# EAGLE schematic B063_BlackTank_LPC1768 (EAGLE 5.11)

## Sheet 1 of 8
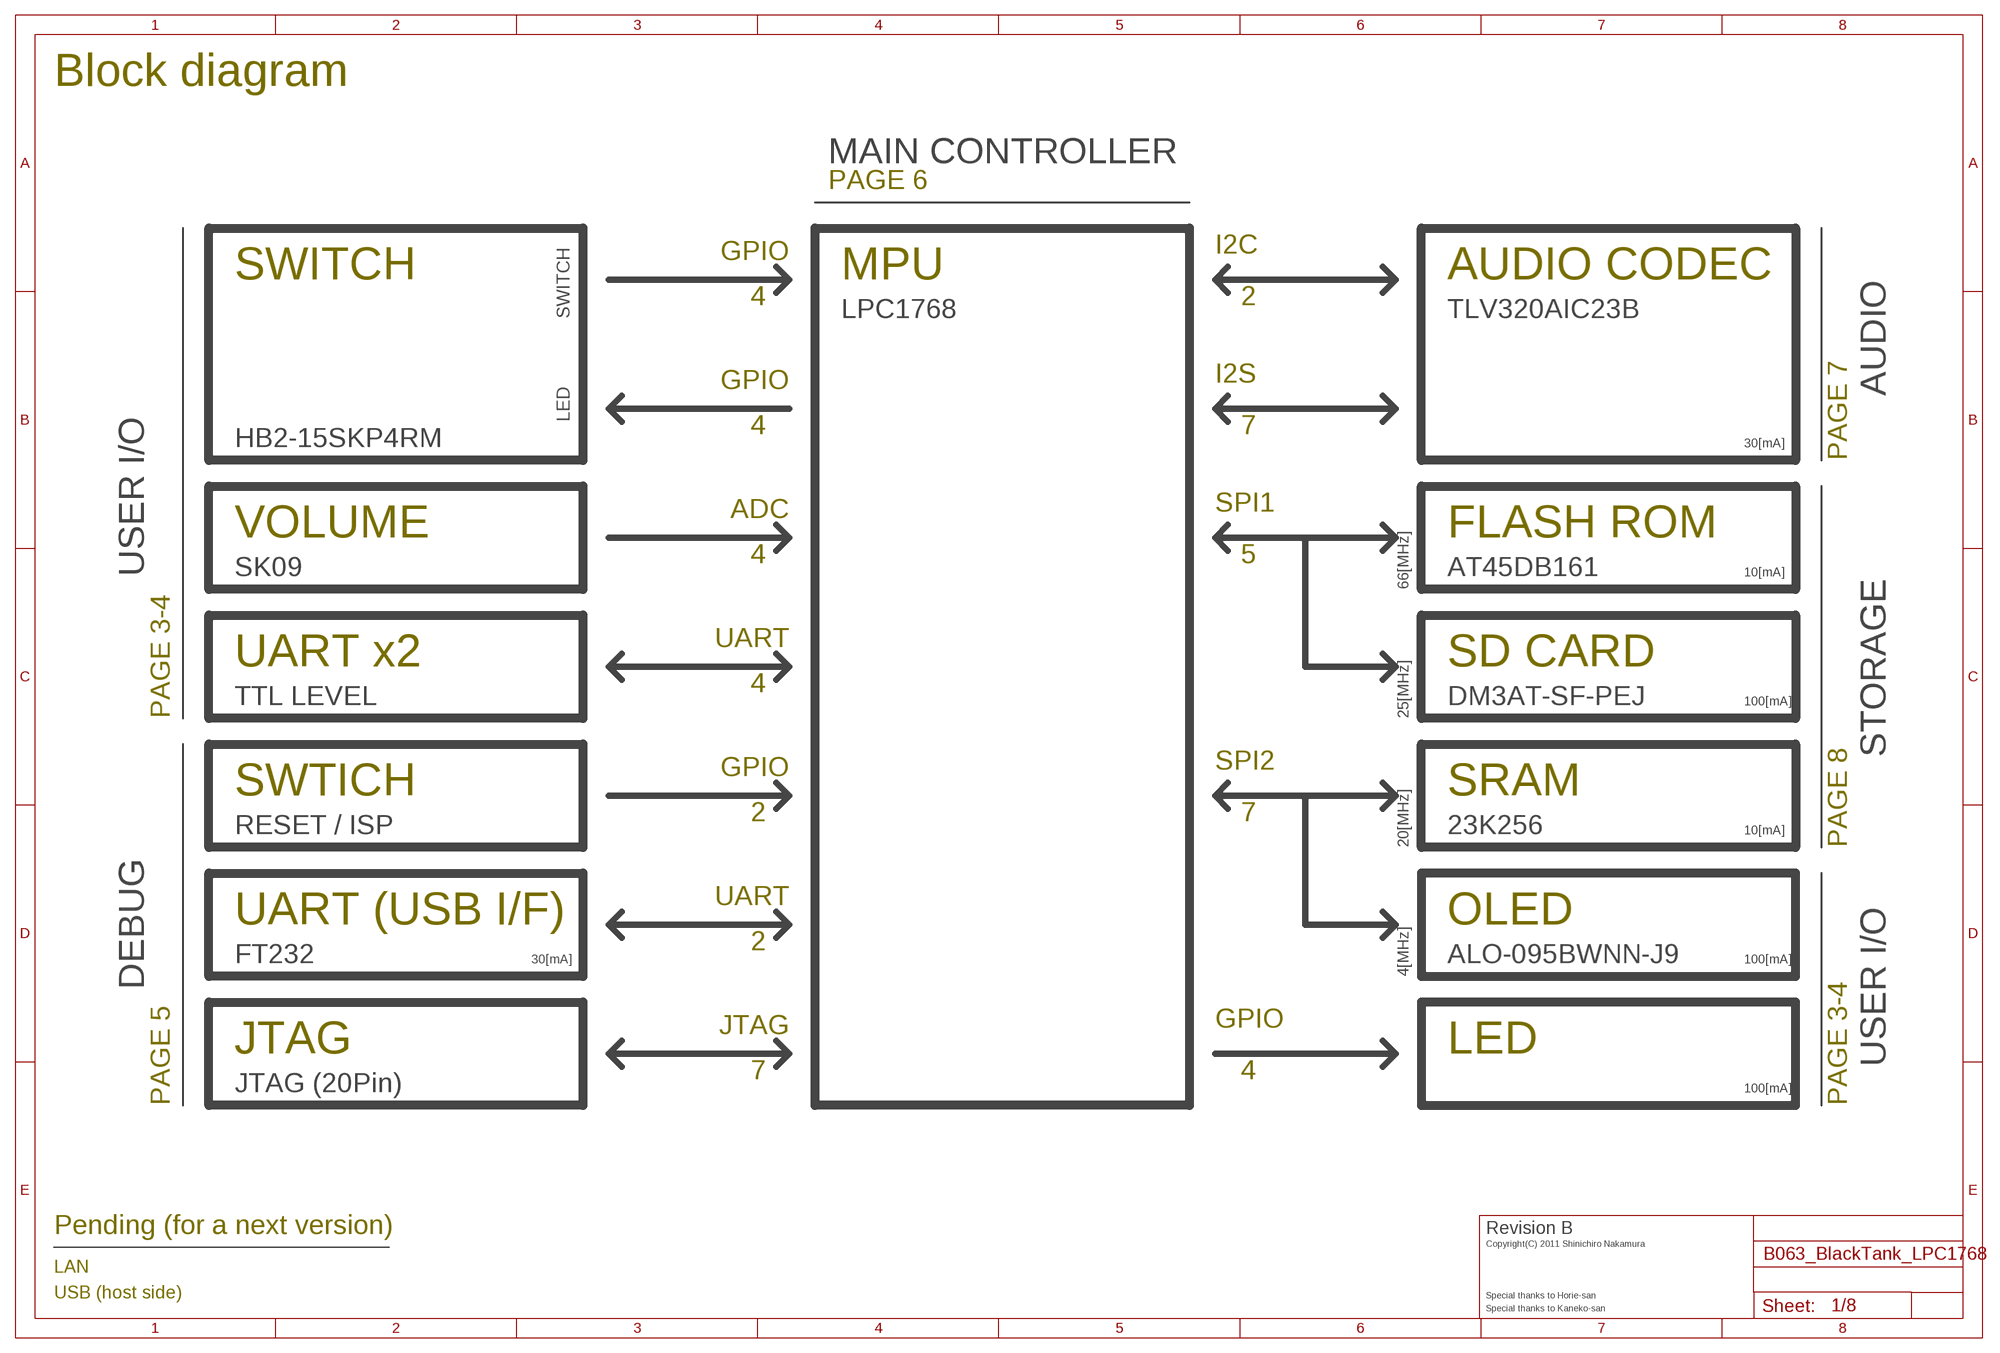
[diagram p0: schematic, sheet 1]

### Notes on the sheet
- Block diagram
- MAIN CONTROLLER
- PAGE 6
- GPIO
- I2C
- SWITCH | MPU | AUDIO CODEC
- 4 | 2
- SWITCH | LPC1768 | TLV320AIC23B
- GPIO
- I2S
- AUDIO
- LED
- 4 | 7
- HB2-15SKP4RM | 30[mA]
- PAGE 7
- ADC
- SPI1
- VOLUME | FLASH ROM
- 4 | 5
- USER I/O | SK09 | AT45DB161 | 10[mA]
- 66[MHz]
- UART
- UART x2 | SD CARD
- 4
- TTL LEVEL | DM3AT-SF-PEJ | 100[mA]
- PAGE 3-4 | 25[MHz]
- GPIO | STORAGE
- SPI2
- SWTICH | SRAM
- 2 | 7
- RESET / ISP | 23K256 | 10[mA]
- 20[MHz] | PAGE 8
- UART
- UART (USB I/F) | OLED
- 2
- FT232 | 30[mA] | ALO-095BWNN-J9 | 100[mA]
- 4[MHz]
- DEBUG
- JTAG
- GPIO
- JTAG | LED
- USER I/O
- 7 | 4
- JTAG (20Pin) | 100[mA]
- PAGE 5 | PAGE 3-4
- Pending (for a next version) | Revision B
- Copyright(C) 2011 Shinichiro Nakamura
- LAN
- USB (host side) | Special thanks to Horie-san
- Special thanks to Kaneko-san

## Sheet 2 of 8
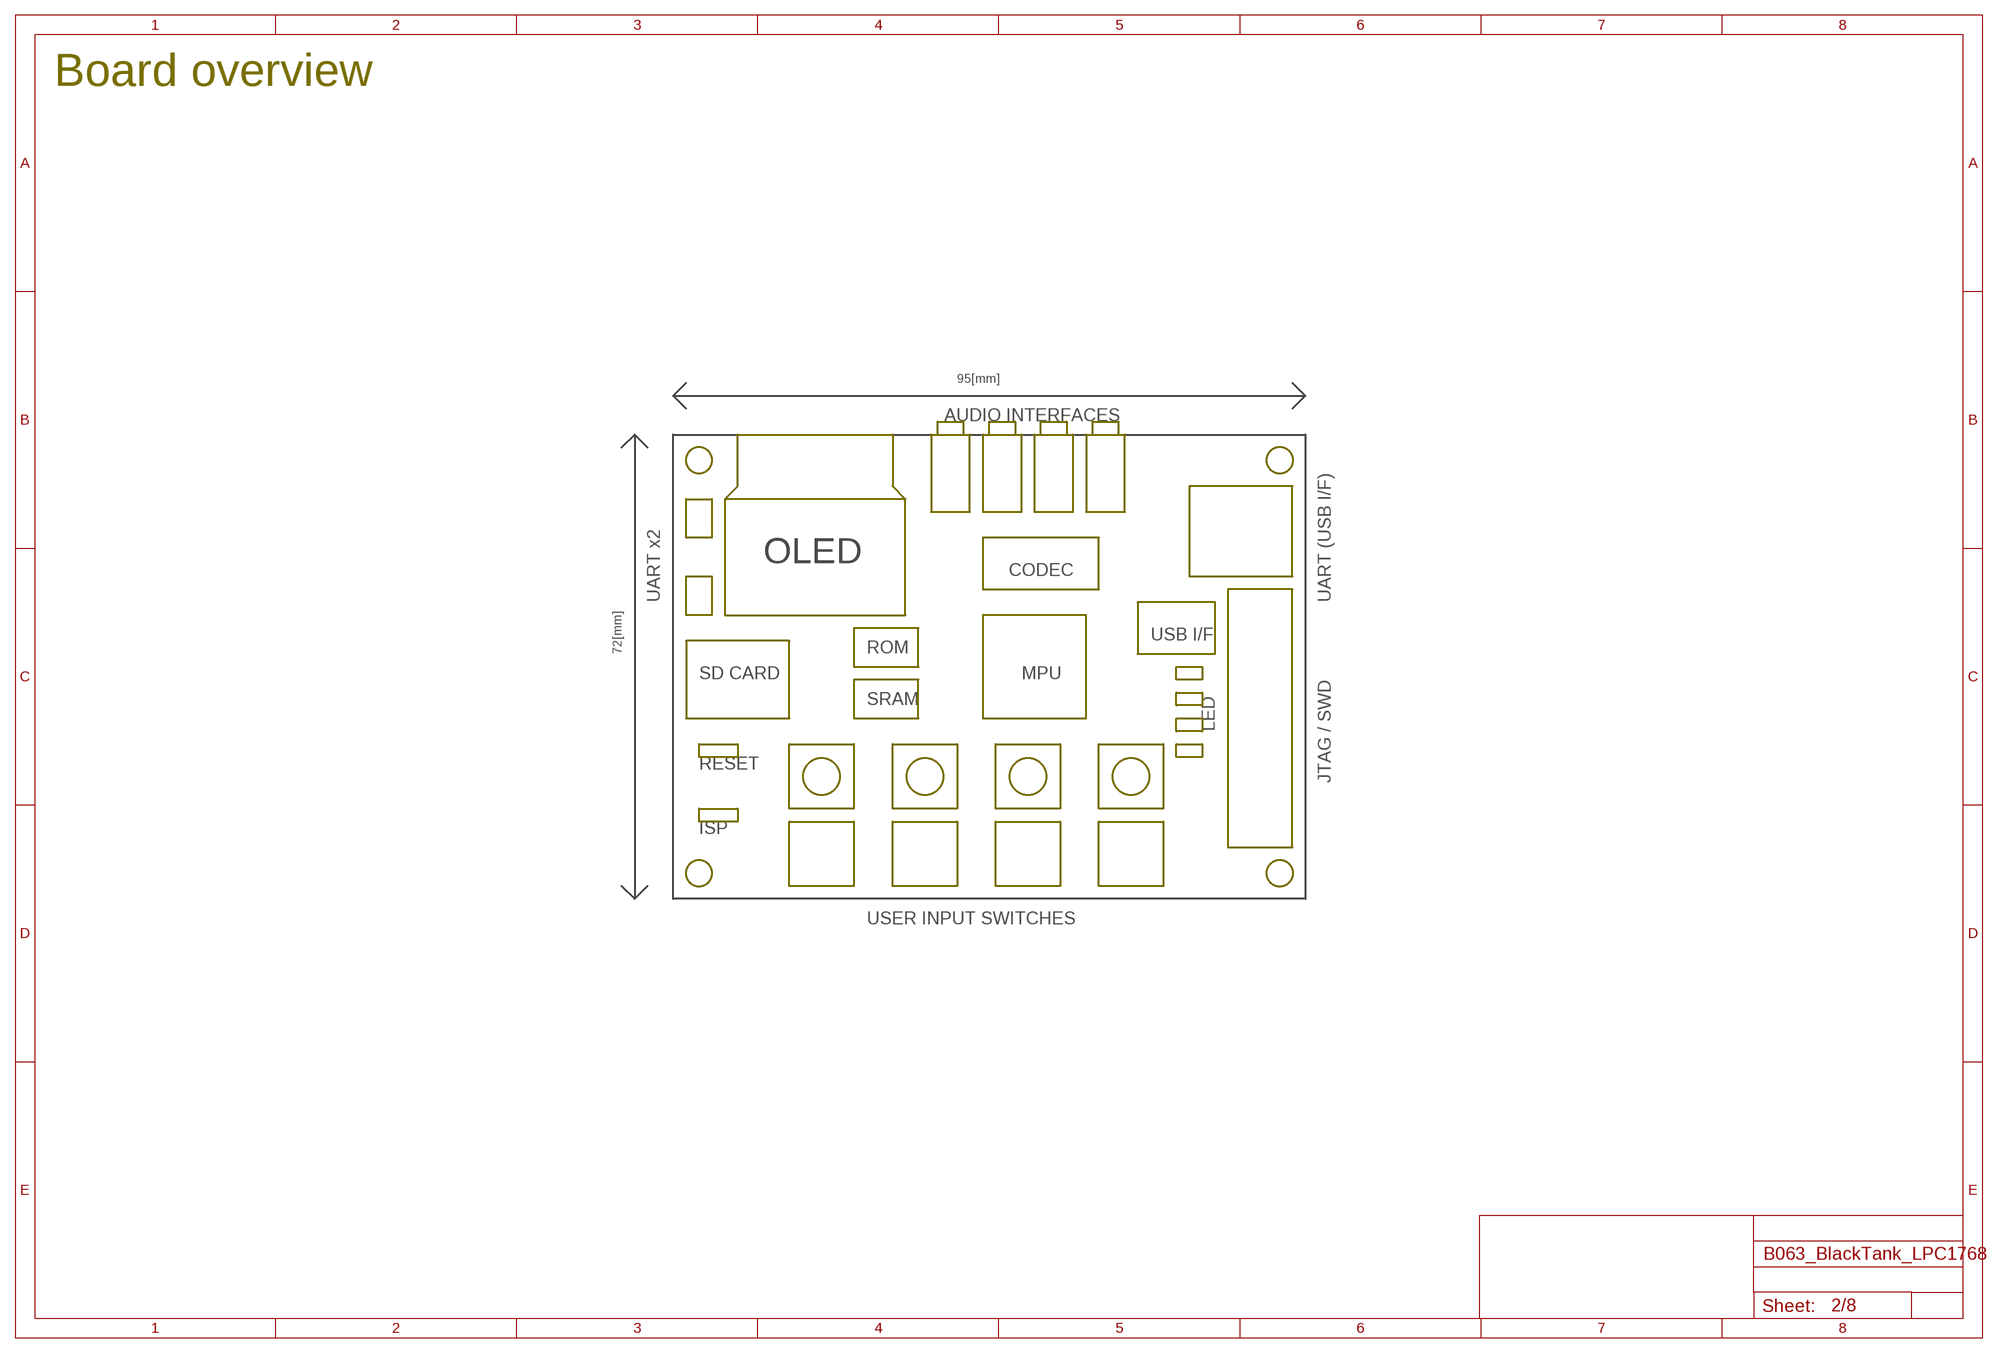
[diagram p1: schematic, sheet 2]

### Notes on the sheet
- Board overview
- 95[mm]
- AUDIO INTERFACES
- OLED
- CODEC
- UART x2 | UART (USB I/F)
- USB I/F
- 72[mm] | ROM
- SD CARD | MPU
- SRAM
- LED
- RESET
- JTAG / SWD
- ISP
- USER INPUT SWITCHES

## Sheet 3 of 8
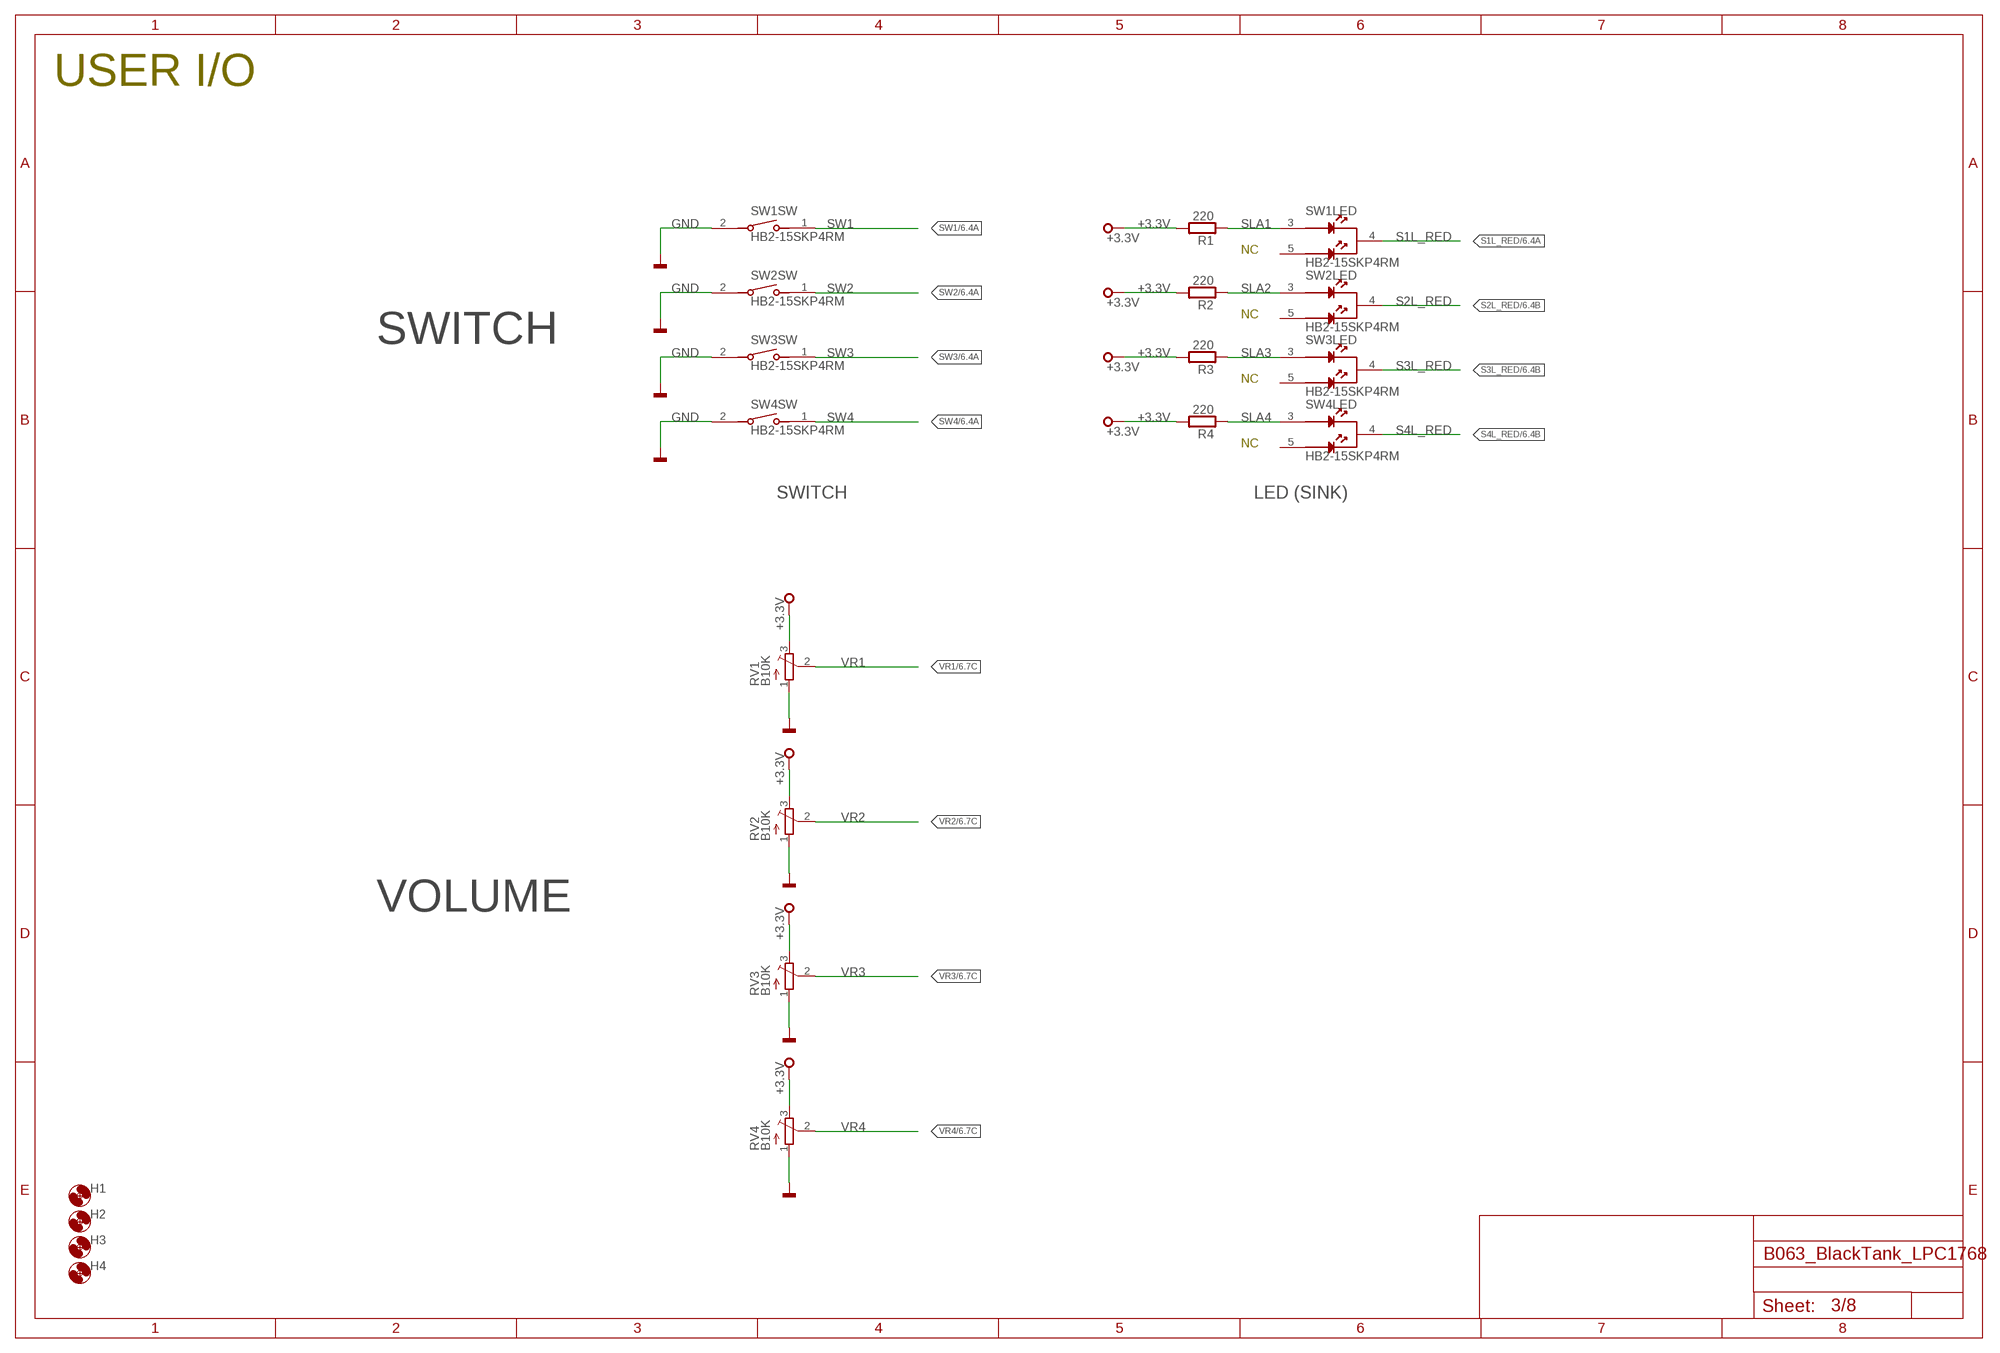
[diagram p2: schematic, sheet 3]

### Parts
H1  MOUNT-HOLE3.2  [3,2]
H2  MOUNT-HOLE3.2  [3,2]
H3  MOUNT-HOLE3.2  [3,2]
H4  MOUNT-HOLE3.2  [3,2]
R1  220  R0603  [0603]
R2  220  R0603  [0603]
R3  220  R0603  [0603]
R4  220  R0603  [0603]
RV1  B10K  RK09  [SK09]
RV2  B10K  RK09  [SK09]
RV3  B10K  RK09  [SK09]
RV4  B10K  RK09  [SK09]
SW1  HB2-15SKP4RM  [HB2]
SW2  HB2-15SKP4RM  [HB2]
SW3  HB2-15SKP4RM  [HB2]
SW4  HB2-15SKP4RM  [HB2]

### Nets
+3.3V [PWR]: R1.2 R2.2 R3.2 R4.2 RV1.3(R1) RV2.3(R1) RV3.3(R1) RV4.3(R1) ; also sheet 4,5,6,7,8
GND [GND]: RV1.1(R2) RV2.1(R2) RV3.1(R2) RV4.1(R2) SW1.2 SW2.2 SW3.2 SW4.2 ; also sheet 4,5,6,7,8
S1L_RED: SW1.4(LED:C) ; also sheet 6
S2L_RED: SW2.4(LED:C) ; also sheet 6
S3L_RED: SW3.4(LED:C) ; also sheet 6
S4L_RED: SW4.4(LED:C) ; also sheet 6
SLA1: R1.1 SW1.3(LED:A1)
SLA2: R2.1 SW2.3(LED:A1)
SLA3: R3.1 SW3.3(LED:A1)
SLA4: R4.1 SW4.3(LED:A1)
SW1: SW1.1 ; also sheet 6
SW2: SW2.1 ; also sheet 6
SW3: SW3.1 ; also sheet 6
SW4: SW4.1 ; also sheet 6
VR1: RV1.2(P) ; also sheet 6
VR2: RV2.2(P) ; also sheet 6
VR3: RV3.2(P) ; also sheet 6
VR4: RV4.2(P) ; also sheet 6
Unconnected: SW1.5(LED:A2) SW2.5(LED:A2) SW3.5(LED:A2) SW4.5(LED:A2)

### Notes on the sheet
- USER I/O
- NC
- NC
- SWITCH
- NC
- NC
- SWITCH | LED (SINK)
- VOLUME

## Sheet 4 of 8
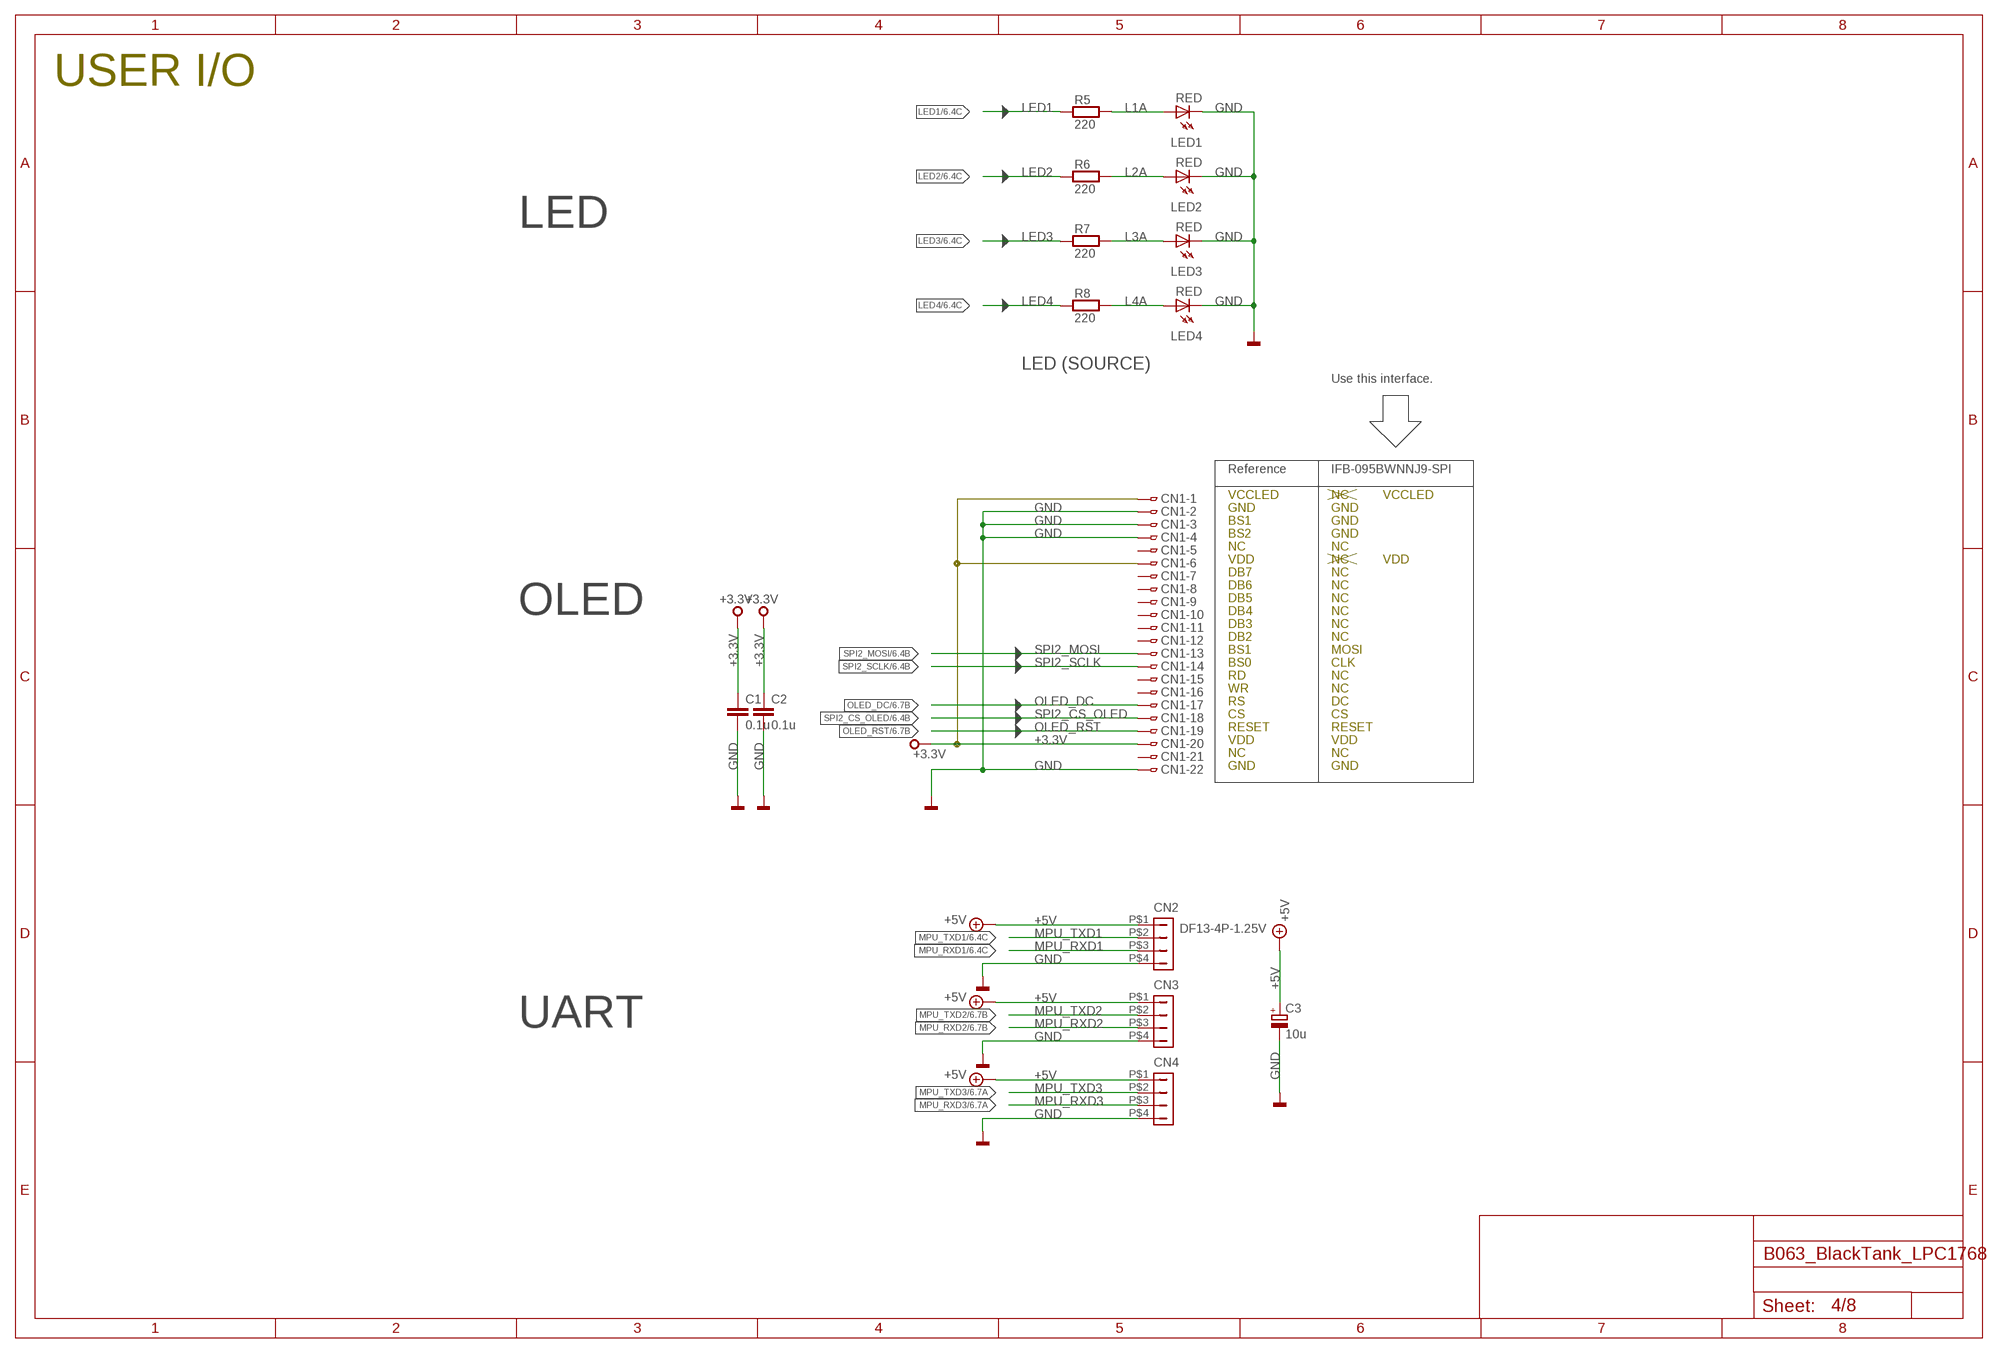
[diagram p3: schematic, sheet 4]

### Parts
C1  0.1u  C-EUC0603  [C0603]
C2  0.1u  C-EUC0603  [C0603]
C3  10u  CPOL-EU153CLV-0505  [153CLV-0505]
CN1  FH12-22S-0.5SH  [FH12-22S-0.5SH]
CN2  DF13-4P-1.25V  [DF13C-4P-1.25V]
CN3  DF13-4P-1.25V  [DF13C-4P-1.25V]
CN4  DF13-4P-1.25V  [DF13C-4P-1.25V]
LED1  RED  LED_0805  [LED_0805]
LED2  RED  LED_0805  [LED_0805]
LED3  RED  LED_0805  [LED_0805]
LED4  RED  LED_0805  [LED_0805]
R5  220  R0603  [0603]
R6  220  R0603  [0603]
R7  220  R0603  [0603]
R8  220  R0603  [0603]

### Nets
+3.3V [PWR]: C1.1 C2.1 CN1.20 ; also sheet 3,5,6,7,8
+5V [PWR]: C3.+ CN2.P$1 CN3.P$1 CN4.P$1 ; also sheet 5
GND [GND]: C1.2 C2.2 C3.- CN1.2 CN1.3 CN1.4 CN1.22 CN2.P$4 CN3.P$4 CN4.P$4 LED1.K LED2.K LED3.K LED4.K ; also sheet 3,5,6,7,8
L1A: LED1.A R5.2
L2A: LED2.A R6.2
L3A: LED3.A R7.2
L4A: LED4.A R8.2
LED1: R5.1 ; also sheet 6
LED2: R6.1 ; also sheet 6
LED3: R7.1 ; also sheet 6
LED4: R8.1 ; also sheet 6
MPU_RXD1: CN2.P$3 ; also sheet 6
MPU_RXD2: CN3.P$3 ; also sheet 6
MPU_RXD3: CN4.P$3 ; also sheet 6
MPU_TXD1: CN2.P$2 ; also sheet 6
MPU_TXD2: CN3.P$2 ; also sheet 6
MPU_TXD3: CN4.P$2 ; also sheet 6
OLED_DC: CN1.17 ; also sheet 6
OLED_RST: CN1.19 ; also sheet 6
SPI2_CS_OLED: CN1.18 ; also sheet 6
SPI2_MOSI: CN1.13 ; also sheet 6,8
SPI2_SCLK: CN1.14 ; also sheet 6,8
Unconnected: CN1.1 CN1.5 CN1.6 CN1.7 CN1.8 CN1.9 CN1.10 CN1.11 CN1.12 CN1.15 CN1.16 CN1.21

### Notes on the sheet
- USER I/O
- LED
- LED (SOURCE)
- Use this interface.
- Reference | IFB-095BWNNJ9-SPI
- VCCLED | NC | VCCLED
- GND | GND
- BS1 | GND
- BS2 | GND
- NC | NC
- VDD | NC | VDD
- DB7 | NC
- DB6 | NC
- DB5 | NC
- OLED | DB4 | NC
- DB3 | NC
- DB2 | NC
- BS1 | MOSI
- BS0 | CLK
- RD | NC
- WR | NC
- RS | DC
- CS | CS
- RESET | RESET
- VDD | VDD
- NC | NC
- GND | GND
- UART

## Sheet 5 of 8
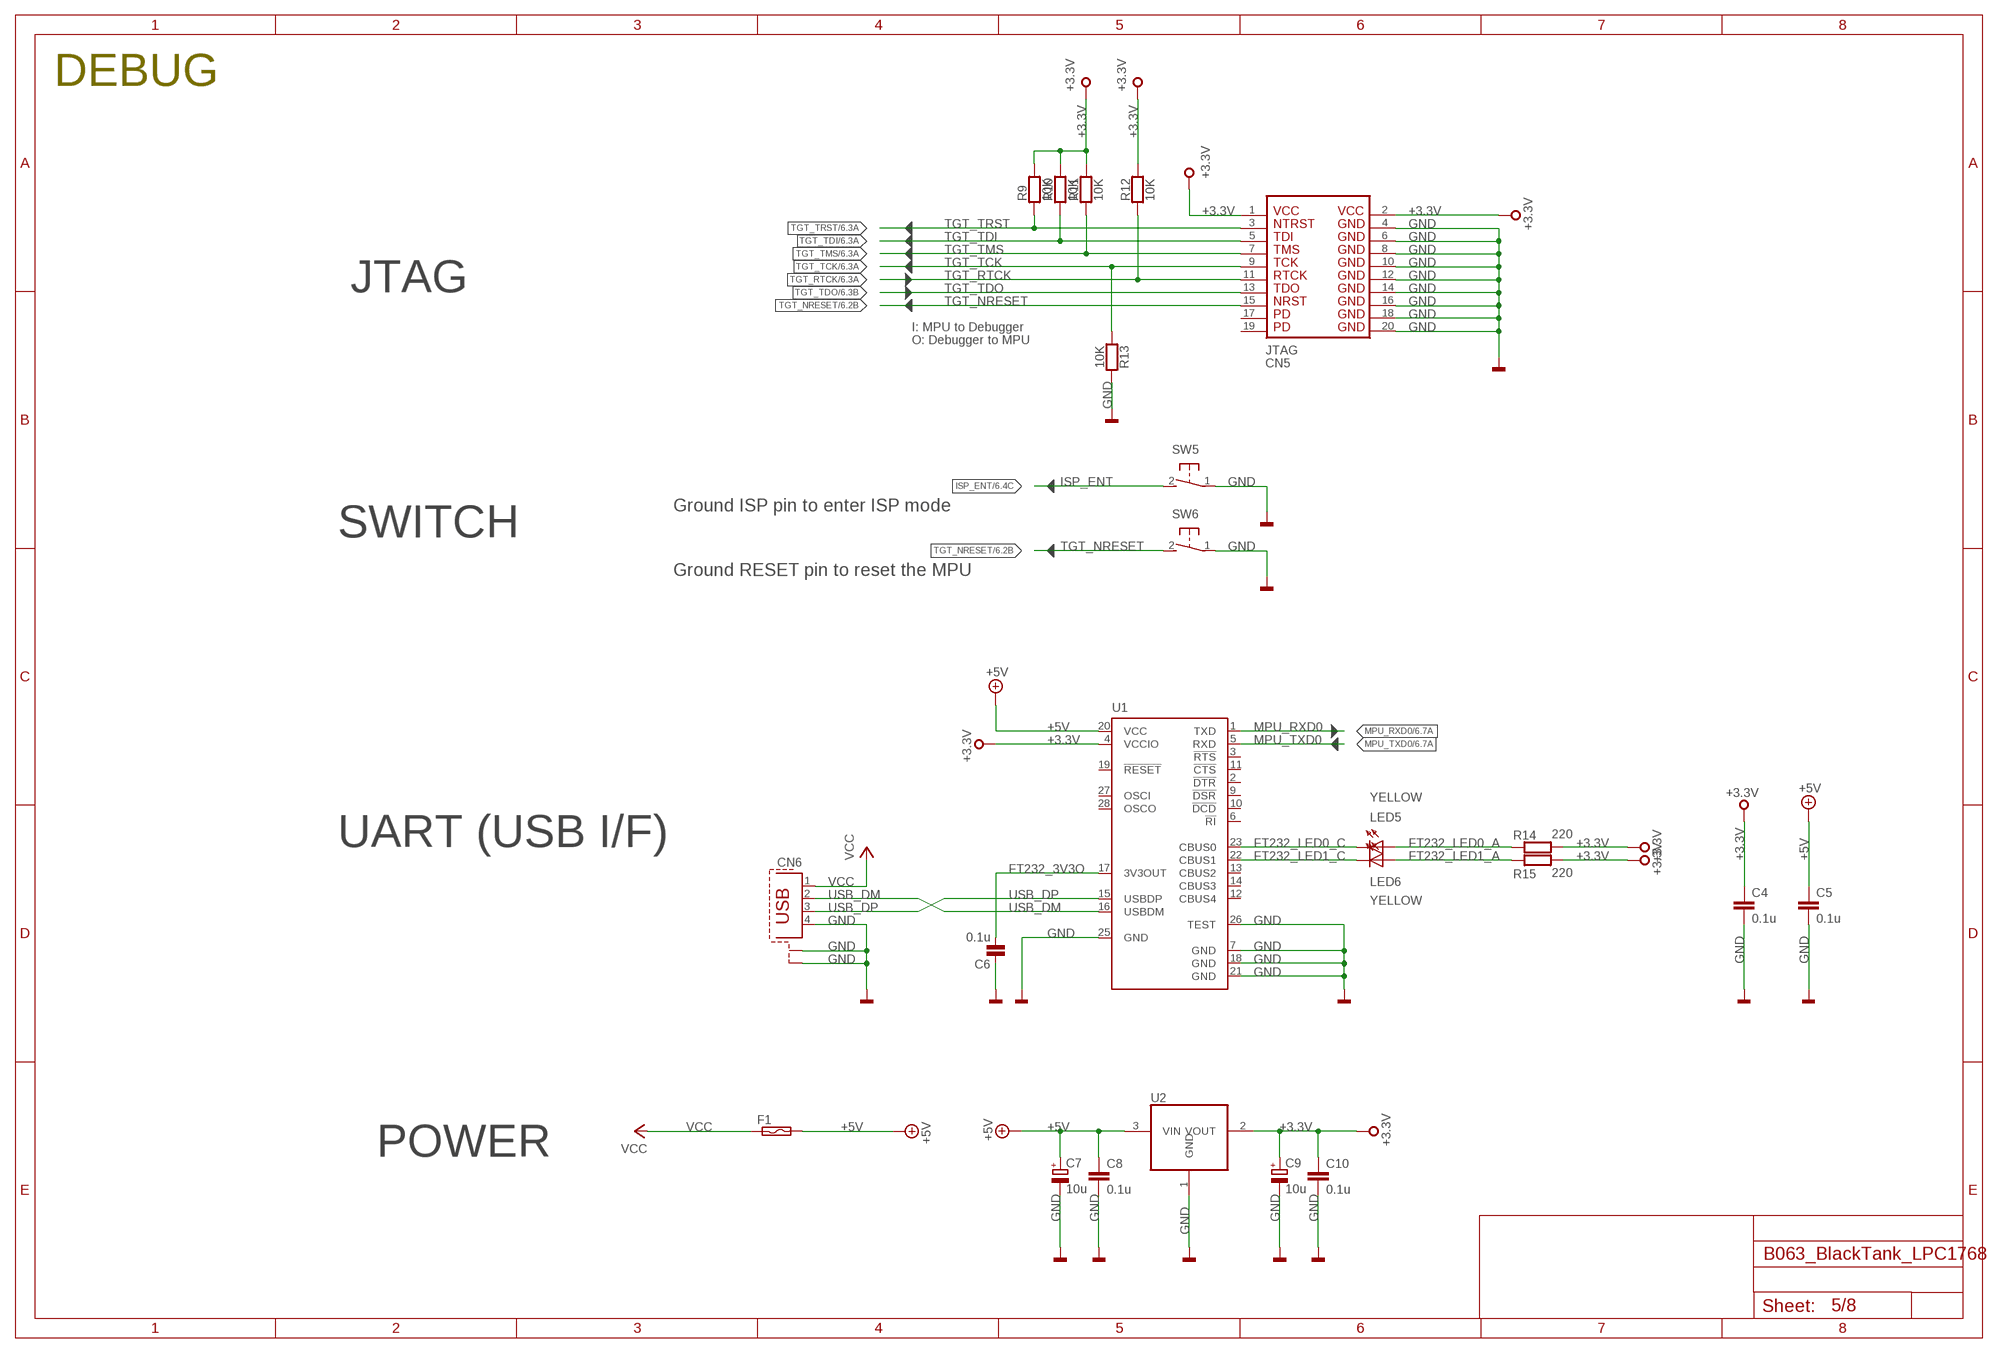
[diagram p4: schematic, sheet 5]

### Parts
C4  0.1u  C-EUC0603  [C0603]
C5  0.1u  C-EUC0603  [C0603]
C6  0.1u  C0603  [0603]
C7  10u  CPOL-EU153CLV-0505  [153CLV-0505]
C8  0.1u  C-EUC0603  [C0603]
C9  10u  CPOL-EU153CLV-0505  [153CLV-0505]
C10  0.1u  C-EUC0603  [C0603]
CN5  JTAG-20  [JTAG-20]
CN6  PN61729-S  [PN61729-S]
F1  SMD075F  [SMD050F]
LED5  YELLOW  LED_0805  [LED_0805]
LED6  YELLOW  LED_0805  [LED_0805]
R9  10K  R0603  [0603]
R10  10K  R0603  [0603]
R11  10K  R0603  [0603]
R12  10K  R0603  [0603]
R13  10K  R0603  [0603]
R14  220  R0603  [0603]
R15  220  R0603  [0603]
SW5  DTSM-3  [DTSM-3]
SW6  DTSM-3  [DTSM-3]
U1  FT232RL  [SSOP28]
U2  REG1117  [SOT223]

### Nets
+3.3V [PWR]: C4.1 C9.+ C10.1 CN5.1 CN5.2 R9.2 R10.2 R11.2 R12.2 R14.1 R15.1 U1.4(VCCIO) U2.2(VOUT) ; also sheet 3,4,6,7,8
+5V [PWR]: C5.1 C7.+ C8.1 F1.2 U1.20(VCC) U2.3(VIN) ; also sheet 4
FT232_3V3O: C6.2 U1.17(3V3OUT)
FT232_LED0_A: LED5.A R14.2
FT232_LED0_C: LED5.K U1.23(CBUS0)
FT232_LED1_A: LED6.A R15.2
FT232_LED1_C: LED6.K U1.22(CBUS1)
GND [GND]: C4.2 C5.2 C6.1 C7.- C8.2 C9.- C10.2 CN5.4 CN5.6 CN5.8 CN5.10 CN5.12 CN5.14 CN5.16 CN5.18 CN5.20 CN6.4 CN6.S1 CN6.S2 R13.2 SW5.1 SW6.1 U1.7(GND) U1.18(GND) U1.21(GND) U1.25(GND) U1.26(TEST) U2.1(GND) ; also sheet 3,4,6,7,8
ISP_ENT: SW5.2 ; also sheet 6
MPU_RXD0: U1.1(TXD) ; also sheet 6
MPU_TXD0: U1.5(RXD) ; also sheet 6
TGT_NRESET: CN5.15 SW6.2 ; also sheet 6
TGT_RTCK: CN5.11 R12.1 ; also sheet 6
TGT_TCK: CN5.9 R13.1 ; also sheet 6
TGT_TDI: CN5.5 R10.1 ; also sheet 6
TGT_TDO: CN5.13 ; also sheet 6
TGT_TMS: CN5.7 R11.1 ; also sheet 6
TGT_TRST: CN5.3 R9.1 ; also sheet 6
USB_DM: CN6.2 U1.16(USBDM)
USB_DP: CN6.3 U1.15(USBDP)
VCC [PWR]: CN6.1 F1.1
Unconnected: CN5.17 CN5.19 U1.2(!DTR) U1.3(!RTS) U1.6(!RI) U1.9(!DSR) U1.10(!DCD) U1.11(!CTS) U1.12(CBUS4) U1.13(CBUS2) U1.14(CBUS3) U1.19(!RESET) U1.27(OSCI) U1.28(OSCO)

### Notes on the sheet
- DEBUG
- JTAG
- I: MPU to Debugger
- O: Debugger to MPU
- Ground ISP pin to enter ISP mode
- SWITCH
- Ground RESET pin to reset the MPU
- UART (USB I/F)
- POWER

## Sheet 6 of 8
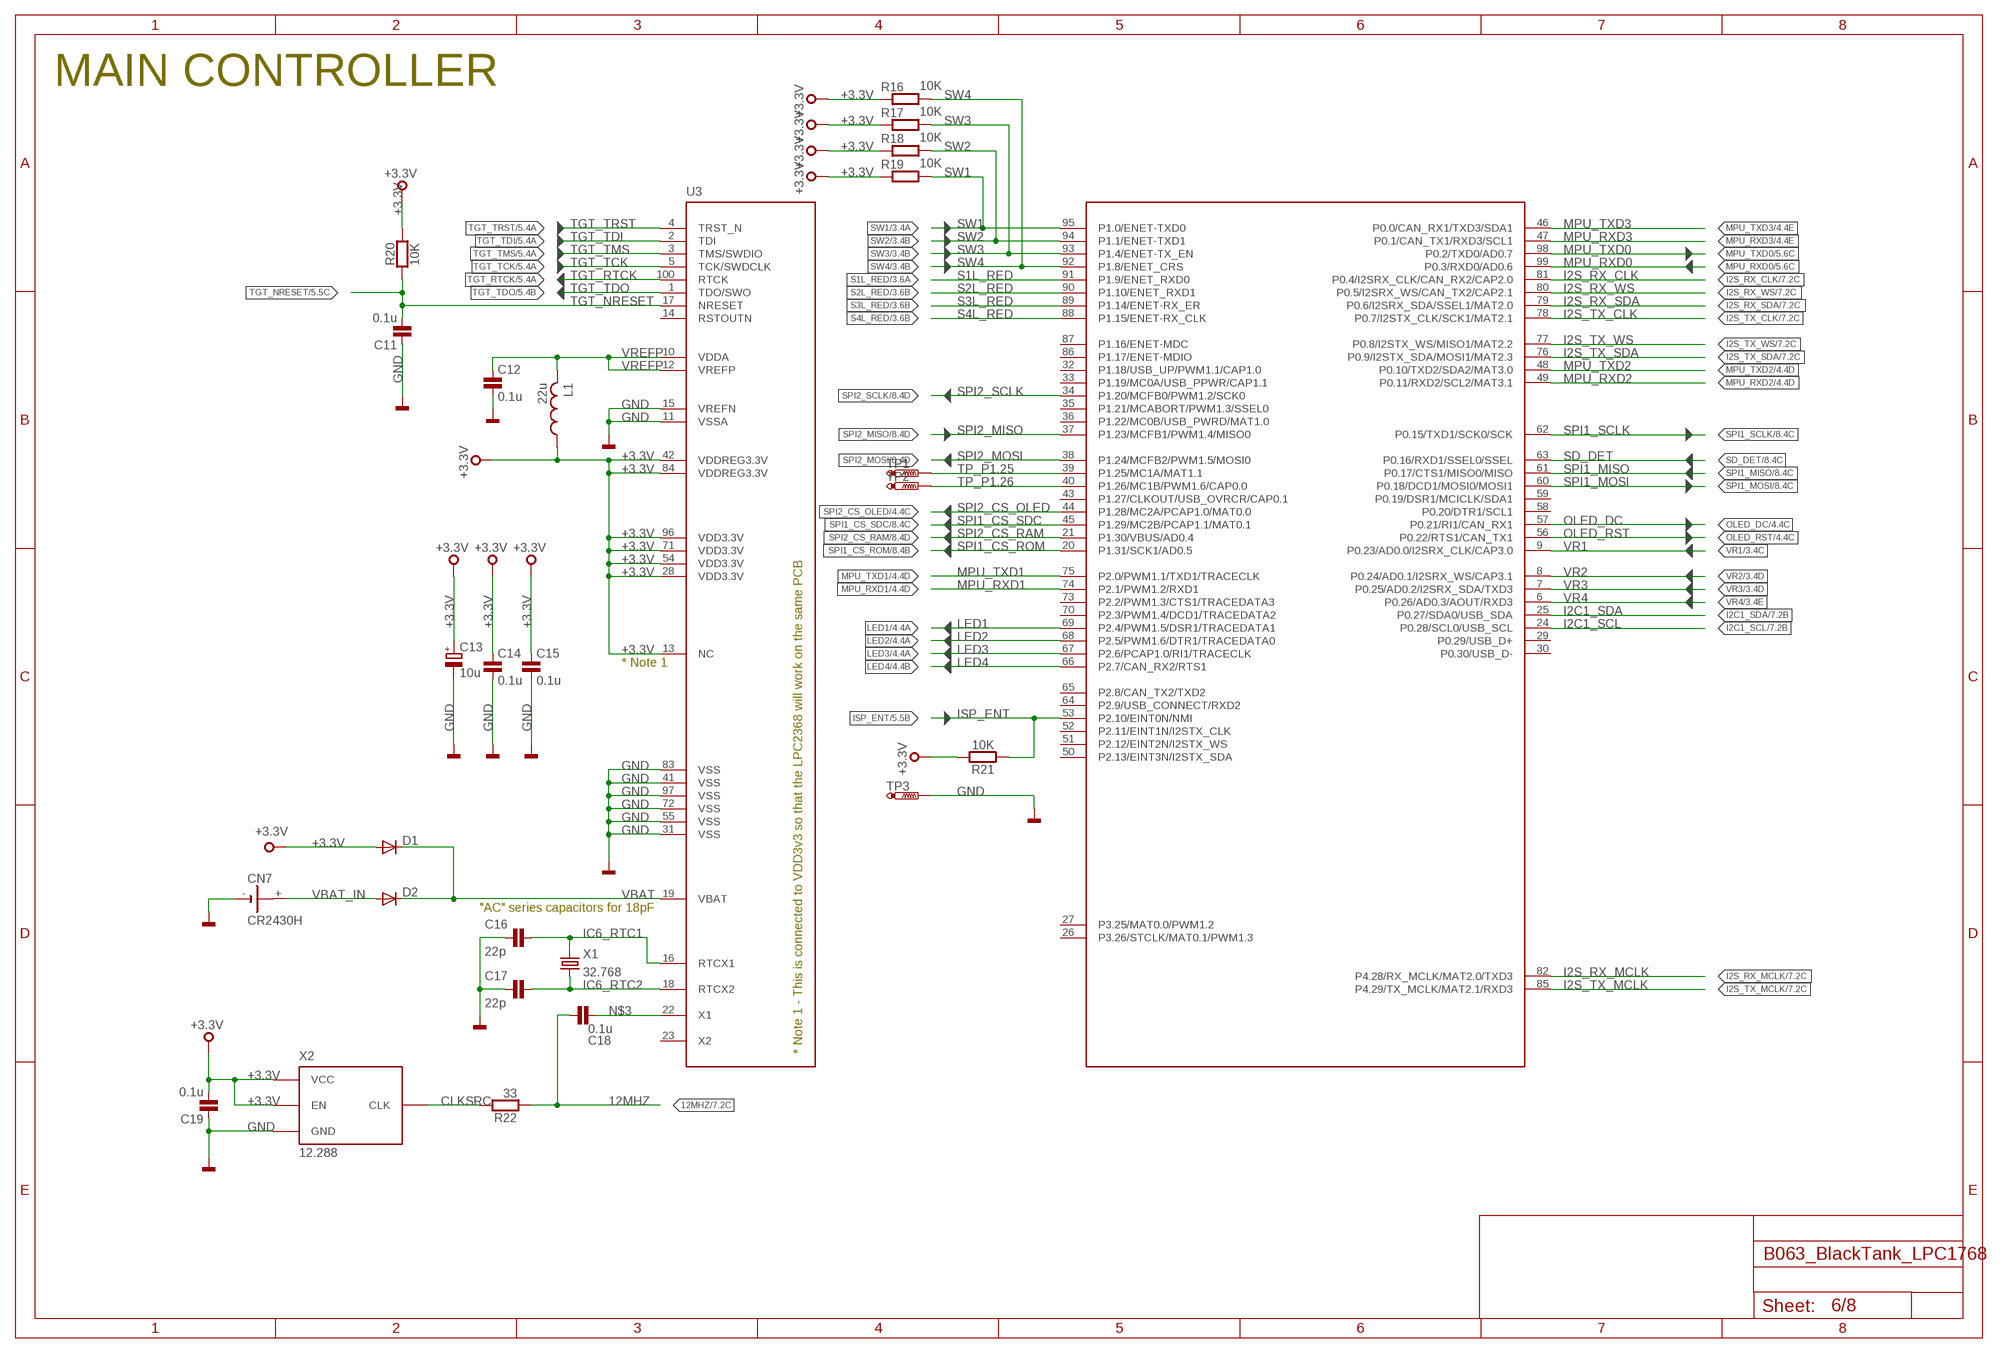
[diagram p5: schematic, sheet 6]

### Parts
C11  0.1u  C0603  [0603]
C12  0.1u  C0603  [0603]
C13  10u  CPOL-EU153CLV-0505  [153CLV-0505]
C14  0.1u  C0603  [0603]
C15  0.1u  C0603  [0603]
C16  22p  C0603  [0603]
C17  22p  C0603  [0603]
C18  0.1u  C0603  [0603]
C19  0.1u  C0603  [0603]
CN7  CR2430H  [CR2430H]
D1  MBR0520LT  [SOD123]
D2  MBR0520LT  [SOD123]
L1  22u  L-USL3230M  [L3230M]
R16  10K  R0603  [0603]
R17  10K  R0603  [0603]
R18  10K  R0603  [0603]
R19  10K  R0603  [0603]
R20  10K  R0603  [0603]
R21  10K  R0603  [0603]
R22  33  R0603  [0603]
TP1  PTR1PAD1-13  [P1-13]
TP2  PTR1PAD1-13  [P1-13]
TP3  PTR1PAD1-13  [P1-13]
U3  LPC1768  [LQFP100]
X1  32.768  CRYSTALFC135  [FC135]
X2  12.288  OSCILLATOR_2.5X3.2  [OSC3.2X.2.5]

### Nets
12MHZ: C18.1 R22.1 ; also sheet 7
+3.3V [PWR]: C13.+ C14.1 C15.1 C19.2 D1.A L1.1 R16.2 R17.2 R18.2 R19.2 R20.2 R21.2 U3.13(NC) U3.28(VDD3.3V) U3.42(VDDREG3.3V) U3.54(VDD3.3V) U3.71(VDD3.3V) U3.84(VDDREG3.3V) U3.96(VDD3.3V) X2.P$1(EN) X2.P$4(VCC) ; also sheet 3,4,5,7,8
CLKSRC: R22.2 X2.P$3(CLK)
GND [GND]: C11.1 C12.2 C13.- C14.2 C15.2 C16.1 C17.1 C19.1 CN7.- TP3.TP U3.11(VSSA) U3.15(VREFN) U3.31(VSS) U3.41(VSS) U3.55(VSS) U3.72(VSS) U3.83(VSS) U3.97(VSS) X2.P$2(GND) ; also sheet 3,4,5,7,8
I2C1_SCL: U3.24(P0.28/SCL0/USB_SCL) ; also sheet 7
I2C1_SDA: U3.25(P0.27/SDA0/USB_SDA) ; also sheet 7
I2S_RX_CLK: U3.81(P0.4/I2SRX_CLK/CAN_RX2/CAP2.0) ; also sheet 7
I2S_RX_MCLK: U3.82(P4.28/RX_MCLK/MAT2.0/TXD3) ; also sheet 7
I2S_RX_SDA: U3.79(P0.6/I2SRX_SDA/SSEL1/MAT2.0) ; also sheet 7
I2S_RX_WS: U3.80(P0.5/I2SRX_WS/CAN_TX2/CAP2.1) ; also sheet 7
I2S_TX_CLK: U3.78(P0.7/I2STX_CLK/SCK1/MAT2.1) ; also sheet 7
I2S_TX_MCLK: U3.85(P4.29/TX_MCLK/MAT2.1/RXD3) ; also sheet 7
I2S_TX_SDA: U3.76(P0.9/I2STX_SDA/MOSI1/MAT2.3) ; also sheet 7
I2S_TX_WS: U3.77(P0.8/I2STX_WS/MISO1/MAT2.2) ; also sheet 7
IC6_RTC1: C16.2 U3.16(RTCX1) X1.X2
IC6_RTC2: C17.2 U3.18(RTCX2) X1.X1
ISP_ENT: R21.1 U3.53(P2.10/EINT0N/NMI) ; also sheet 5
LED1: U3.69(P2.4/PWM1.5/DSR1/TRACEDATA1) ; also sheet 4
LED2: U3.68(P2.5/PWM1.6/DTR1/TRACEDATA0) ; also sheet 4
LED3: U3.67(P2.6/PCAP1.0/RI1/TRACECLK) ; also sheet 4
LED4: U3.66(P2.7/CAN_RX2/RTS1) ; also sheet 4
MPU_RXD0: U3.99(P0.3/RXD0/AD0.6) ; also sheet 5
MPU_RXD1: U3.74(P2.1/PWM1.2/RXD1) ; also sheet 4
MPU_RXD2: U3.49(P0.11/RXD2/SCL2/MAT3.1) ; also sheet 4
MPU_RXD3: U3.47(P0.1/CAN_TX1/RXD3/SCL1) ; also sheet 4
MPU_TXD0: U3.98(P0.2/TXD0/AD0.7) ; also sheet 5
MPU_TXD1: U3.75(P2.0/PWM1.1/TXD1/TRACECLK) ; also sheet 4
MPU_TXD2: U3.48(P0.10/TXD2/SDA2/MAT3.0) ; also sheet 4
MPU_TXD3: U3.46(P0.0/CAN_RX1/TXD3/SDA1) ; also sheet 4
N$3: C18.2 U3.22(X1)
OLED_DC: U3.57(P0.21/RI1/CAN_RX1) ; also sheet 4
OLED_RST: U3.56(P0.22/RTS1/CAN_TX1) ; also sheet 4
S1L_RED: U3.91(P1.9/ENET_RXD0) ; also sheet 3
S2L_RED: U3.90(P1.10/ENET_RXD1) ; also sheet 3
S3L_RED: U3.89(P1.14/ENET-RX_ER) ; also sheet 3
S4L_RED: U3.88(P1.15/ENET-RX_CLK) ; also sheet 3
SD_DET: U3.63(P0.16/RXD1/SSEL0/SSEL) ; also sheet 8
SPI1_CS_ROM: U3.20(P1.31/SCK1/AD0.5) ; also sheet 8
SPI1_CS_SDC: U3.45(P1.29/MC2B/PCAP1.1/MAT0.1) ; also sheet 8
SPI1_MISO: U3.61(P0.17/CTS1/MISO0/MISO) ; also sheet 8
SPI1_MOSI: U3.60(P0.18/DCD1/MOSI0/MOSI1) ; also sheet 8
SPI1_SCLK: U3.62(P0.15/TXD1/SCK0/SCK) ; also sheet 8
SPI2_CS_OLED: U3.44(P1.28/MC2A/PCAP1.0/MAT0.0) ; also sheet 4
SPI2_CS_RAM: U3.21(P1.30/VBUS/AD0.4) ; also sheet 8
SPI2_MISO: U3.37(P1.23/MCFB1/PWM1.4/MISO0) ; also sheet 8
SPI2_MOSI: U3.38(P1.24/MCFB2/PWM1.5/MOSI0) ; also sheet 4,8
SPI2_SCLK: U3.34(P1.20/MCFB0/PWM1.2/SCK0) ; also sheet 4,8
SW1: R19.1 U3.95(P1.0/ENET-TXD0) ; also sheet 3
SW2: R18.1 U3.94(P1.1/ENET-TXD1) ; also sheet 3
SW3: R17.1 U3.93(P1.4/ENET-TX_EN) ; also sheet 3
SW4: R16.1 U3.92(P1.8/ENET_CRS) ; also sheet 3
TGT_NRESET: C11.2 R20.1 U3.17(NRESET) ; also sheet 5
TGT_RTCK: U3.100(RTCK) ; also sheet 5
TGT_TCK: U3.5(TCK/SWDCLK) ; also sheet 5
TGT_TDI: U3.2(TDI) ; also sheet 5
TGT_TDO: U3.1(TDO/SWO) ; also sheet 5
TGT_TMS: U3.3(TMS/SWDIO) ; also sheet 5
TGT_TRST: U3.4(TRST_N) ; also sheet 5
TP_P1.25: TP1.TP U3.39(P1.25/MC1A/MAT1.1)
TP_P1.26: TP2.TP U3.40(P1.26/MC1B/PWM1.6/CAP0.0)
VBAT [PWR]: D1.C D2.C U3.19(VBAT)
VBAT_IN [PWR]: CN7.+ D2.A
VR1: U3.9(P0.23/AD0.0/I2SRX_CLK/CAP3.0) ; also sheet 3
VR2: U3.8(P0.24/AD0.1/I2SRX_WS/CAP3.1) ; also sheet 3
VR3: U3.7(P0.25/AD0.2/I2SRX_SDA/TXD3) ; also sheet 3
VR4: U3.6(P0.26/AD0.3/AOUT/RXD3) ; also sheet 3
VREFP: C12.1 L1.2 U3.10(VDDA) U3.12(VREFP)
Unconnected: CN7.+@1(+) U3.14(RSTOUTN) U3.23(X2) U3.26(P3.26/STCLK/MAT0.1/PWM1.3) U3.27(P3.25/MAT0.0/PWM1.2) U3.29(P0.29/USB_D+) U3.30(P0.30/USB_D-) U3.32(P1.18/USB_UP/PWM1.1/CAP1.0) U3.33(P1.19/MC0A/USB_PPWR/CAP1.1) U3.35(P1.21/MCABORT/PWM1.3/SSEL0) U3.36(P1.22/MC0B/USB_PWRD/MAT1.0) U3.43(P1.27/CLKOUT/USB_OVRCR/CAP0.1) U3.50(P2.13/EINT3N/I2STX_SDA) U3.51(P2.12/EINT2N/I2STX_WS) U3.52(P2.11/EINT1N/I2STX_CLK) U3.58(P0.20/DTR1/SCL1) U3.59(P0.19/DSR1/MCICLK/SDA1) U3.64(P2.9/USB_CONNECT/RXD2) U3.65(P2.8/CAN_TX2/TXD2) U3.70(P2.3/PWM1.4/DCD1/TRACEDATA2) U3.73(P2.2/PWM1.3/CTS1/TRACEDATA3) U3.86(P1.17/ENET-MDIO) U3.87(P1.16/ENET-MDC)

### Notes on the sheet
- MAIN CONTROLLER
- * Note 1
- "AC" series capacitors for 18pF
- * Note 1 - This is connected to VDD3v3 so that the LPC2368 will work on the same PCB

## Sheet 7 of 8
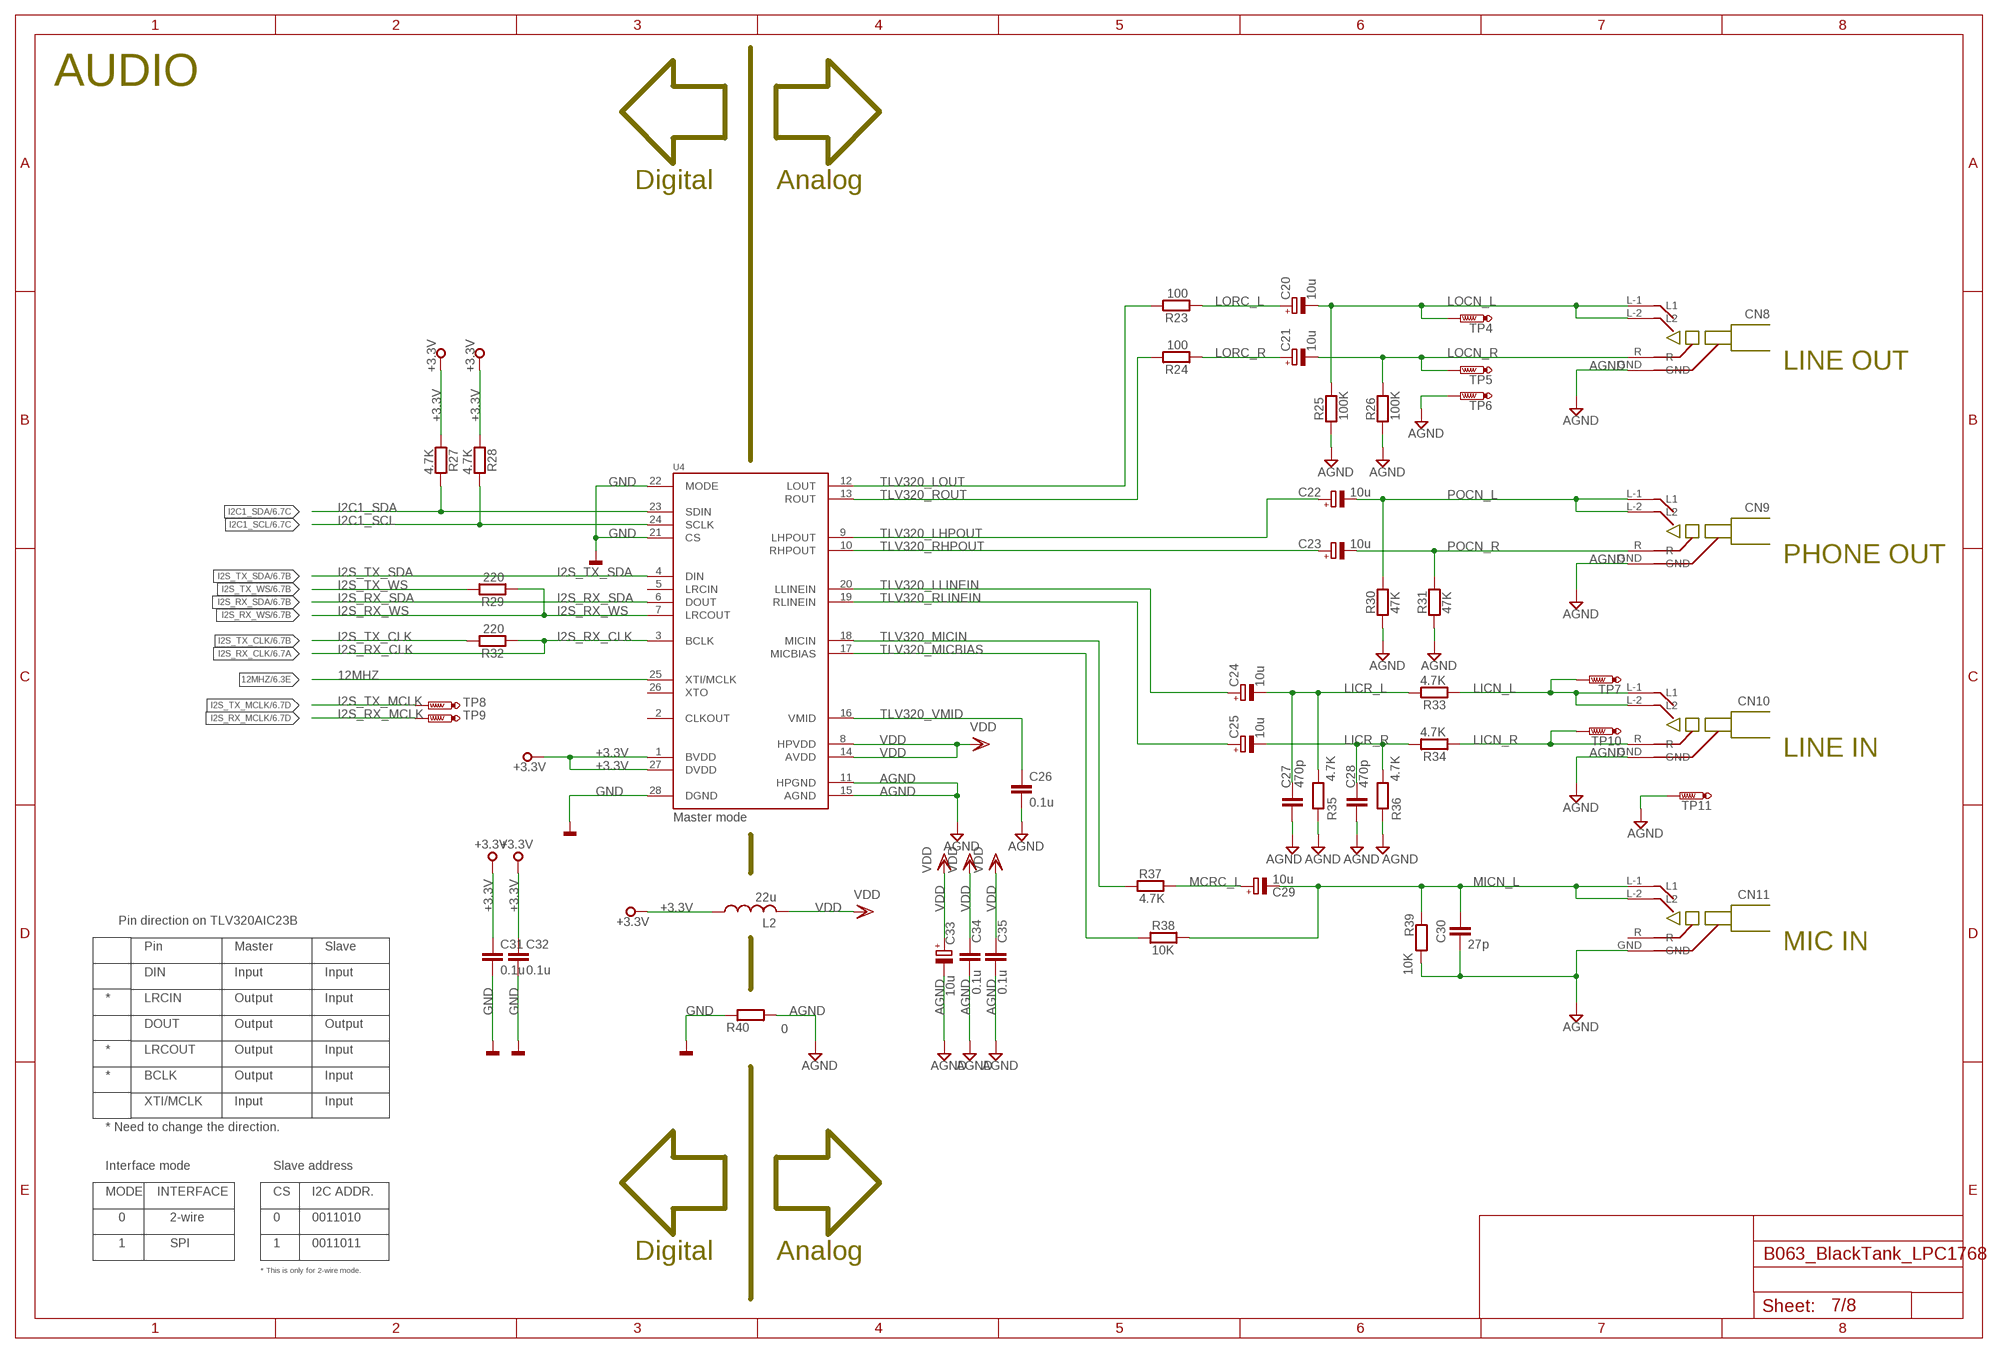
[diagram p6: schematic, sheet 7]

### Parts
C20  10u  CPOL-EU153CLV-0505  [153CLV-0505]
C21  10u  CPOL-EU153CLV-0505  [153CLV-0505]
C22  10u  CPOL-EU153CLV-0505  [153CLV-0505]
C23  10u  CPOL-EU153CLV-0505  [153CLV-0505]
C24  10u  CPOL-EU153CLV-0505  [153CLV-0505]
C25  10u  CPOL-EU153CLV-0505  [153CLV-0505]
C26  0.1u  C-EUC0603  [C0603]
C27  470p  C-EUC0805  [C0805]
C28  470p  C-EUC0805  [C0805]
C29  10u  CPOL-EU153CLV-0505  [153CLV-0505]
C30  27p  C-EUC0805  [C0805]
C31  0.1u  C-EUC0603  [C0603]
C32  0.1u  C-EUC0603  [C0603]
C33  10u  CPOL-EU153CLV-0505  [153CLV-0505]
C34  0.1u  C-EUC0603  [C0603]
C35  0.1u  C-EUC0603  [C0603]
CN8  ST-005  [ST-005]
CN9  ST-005  [ST-005]
CN10  ST-005  [ST-005]
CN11  ST-005  [ST-005]
L2  22u  L-USL3230M  [L3230M]
R23  100  R0603  [0603]
R24  100  R0603  [0603]
R25  100K  R0603  [0603]
R26  100K  R0603  [0603]
R27  4.7K  R0603  [0603]
R28  4.7K  R0603  [0603]
R29  220  R0603  [0603]
R30  47K  R0603  [0603]
R31  47K  R0603  [0603]
R32  220  R0603  [0603]
R33  4.7K  R0603  [0603]
R34  4.7K  R0603  [0603]
R35  4.7K  R0603  [0603]
R36  4.7K  R0603  [0603]
R37  4.7K  R0603  [0603]
R38  10K  R0603  [0603]
R39  10K  R0603  [0603]
R40  0  R0603  [0603]
TP4  PTR1PAD1-13  [P1-13]
TP5  PTR1PAD1-13  [P1-13]
TP6  PTR1PAD1-13  [P1-13]
TP7  PTR1PAD1-13  [P1-13]
TP8  PTR1TP08R  [TP08R]
TP9  PTR1TP08R  [TP08R]
TP10  PTR1PAD1-13  [P1-13]
TP11  PTR1PAD1-13  [P1-13]
U4  TLV320AIC23BPW  [R-PDSO-G28]

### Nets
12MHZ: U4.25(XTI/MCLK) ; also sheet 6
+3.3V [PWR]: C31.1 C32.1 L2.1 R27.1 R28.1 U4.1(BVDD) U4.27(DVDD) ; also sheet 3,4,5,6,8
AGND [GND]: C26.2 C27.2 C28.2 C30.2 C33.- C34.2 C35.2 CN8.GND CN9.GND CN10.GND CN11.GND R25.1 R26.1 R30.1 R31.1 R35.2 R36.2 R39.2 R40.2 TP6.TP TP11.TP U4.11(HPGND) U4.15(AGND)
GND [GND]: C31.2 C32.2 R40.1 U4.21(CS) U4.22(MODE) U4.28(DGND) ; also sheet 3,4,5,6,8
I2C1_SCL: R28.2 U4.24(SCLK) ; also sheet 6
I2C1_SDA: R27.2 U4.23(SDIN) ; also sheet 6
I2S_RX_CLK: R32.1 U4.3(BCLK) ; also sheet 6
I2S_RX_MCLK: TP9.TP ; also sheet 6
I2S_RX_SDA: U4.6(DOUT) ; also sheet 6
I2S_RX_WS: R29.1 U4.7(LRCOUT) ; also sheet 6
I2S_TX_CLK: R32.2 ; also sheet 6
I2S_TX_MCLK: TP8.TP ; also sheet 6
I2S_TX_SDA: U4.4(DIN) ; also sheet 6
I2S_TX_WS: R29.2 ; also sheet 6
LICN_L: CN10.L-1(L1) CN10.L-2(L2) R33.1 TP7.TP
LICN_R: CN10.R R34.1 TP10.TP
LICR_L: C24.- C27.1 R33.2 R35.1
LICR_R: C25.- C28.1 R34.2 R36.1
LOCN_L: C20.- CN8.L-1(L1) CN8.L-2(L2) R25.2 TP4.TP
LOCN_R: C21.- CN8.R R26.2 TP5.TP
LORC_L: C20.+ R23.1
LORC_R: C21.+ R24.1
MCRC_L: C29.+ R37.2
MICN_L: C29.- C30.1 CN11.L-1(L1) CN11.L-2(L2) R38.2 R39.1
POCN_L: C22.- CN9.L-1(L1) CN9.L-2(L2) R30.2
POCN_R: C23.- CN9.R R31.2
TLV320_LHPOUT: C22.+ U4.9(LHPOUT)
TLV320_LLINEIN: C24.+ U4.20(LLINEIN)
TLV320_LOUT: R23.2 U4.12(LOUT)
TLV320_MICBIAS: R38.1 U4.17(MICBIAS)
TLV320_MICIN: R37.1 U4.18(MICIN)
TLV320_RHPOUT: C23.+ U4.10(RHPOUT)
TLV320_RLINEIN: C25.+ U4.19(RLINEIN)
TLV320_ROUT: R24.2 U4.13(ROUT)
TLV320_VMID: C26.1 U4.16(VMID)
VDD [PWR]: C33.+ C34.1 C35.1 L2.2 U4.8(HPVDD) U4.14(AVDD)
Unconnected: CN11.R U4.2(CLKOUT) U4.5(LRCIN) U4.26(XTO)

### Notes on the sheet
- AUDIO
- Digital | Analog
- LINE OUT
- PHONE OUT
- LINE IN
- Master mode
- Pin direction on TLV320AIC23B
- Pin | Master | Slave | MIC IN
- DIN | Input | Input
- * | LRCIN | Output | Input
- DOUT | Output | Output
- * | LRCOUT | Output | Input
- * | BCLK | Output | Input
- XTI/MCLK | Input | Input
- * Need to change the direction.
- Interface mode | Slave address
- MODE | INTERFACE | CS | I2C ADDR.
- 0 | 2-wire | 0 | 0011010
- 1 | SPI | 1 | 0011011
- Digital | Analog
- * This is only for 2-wire mode.

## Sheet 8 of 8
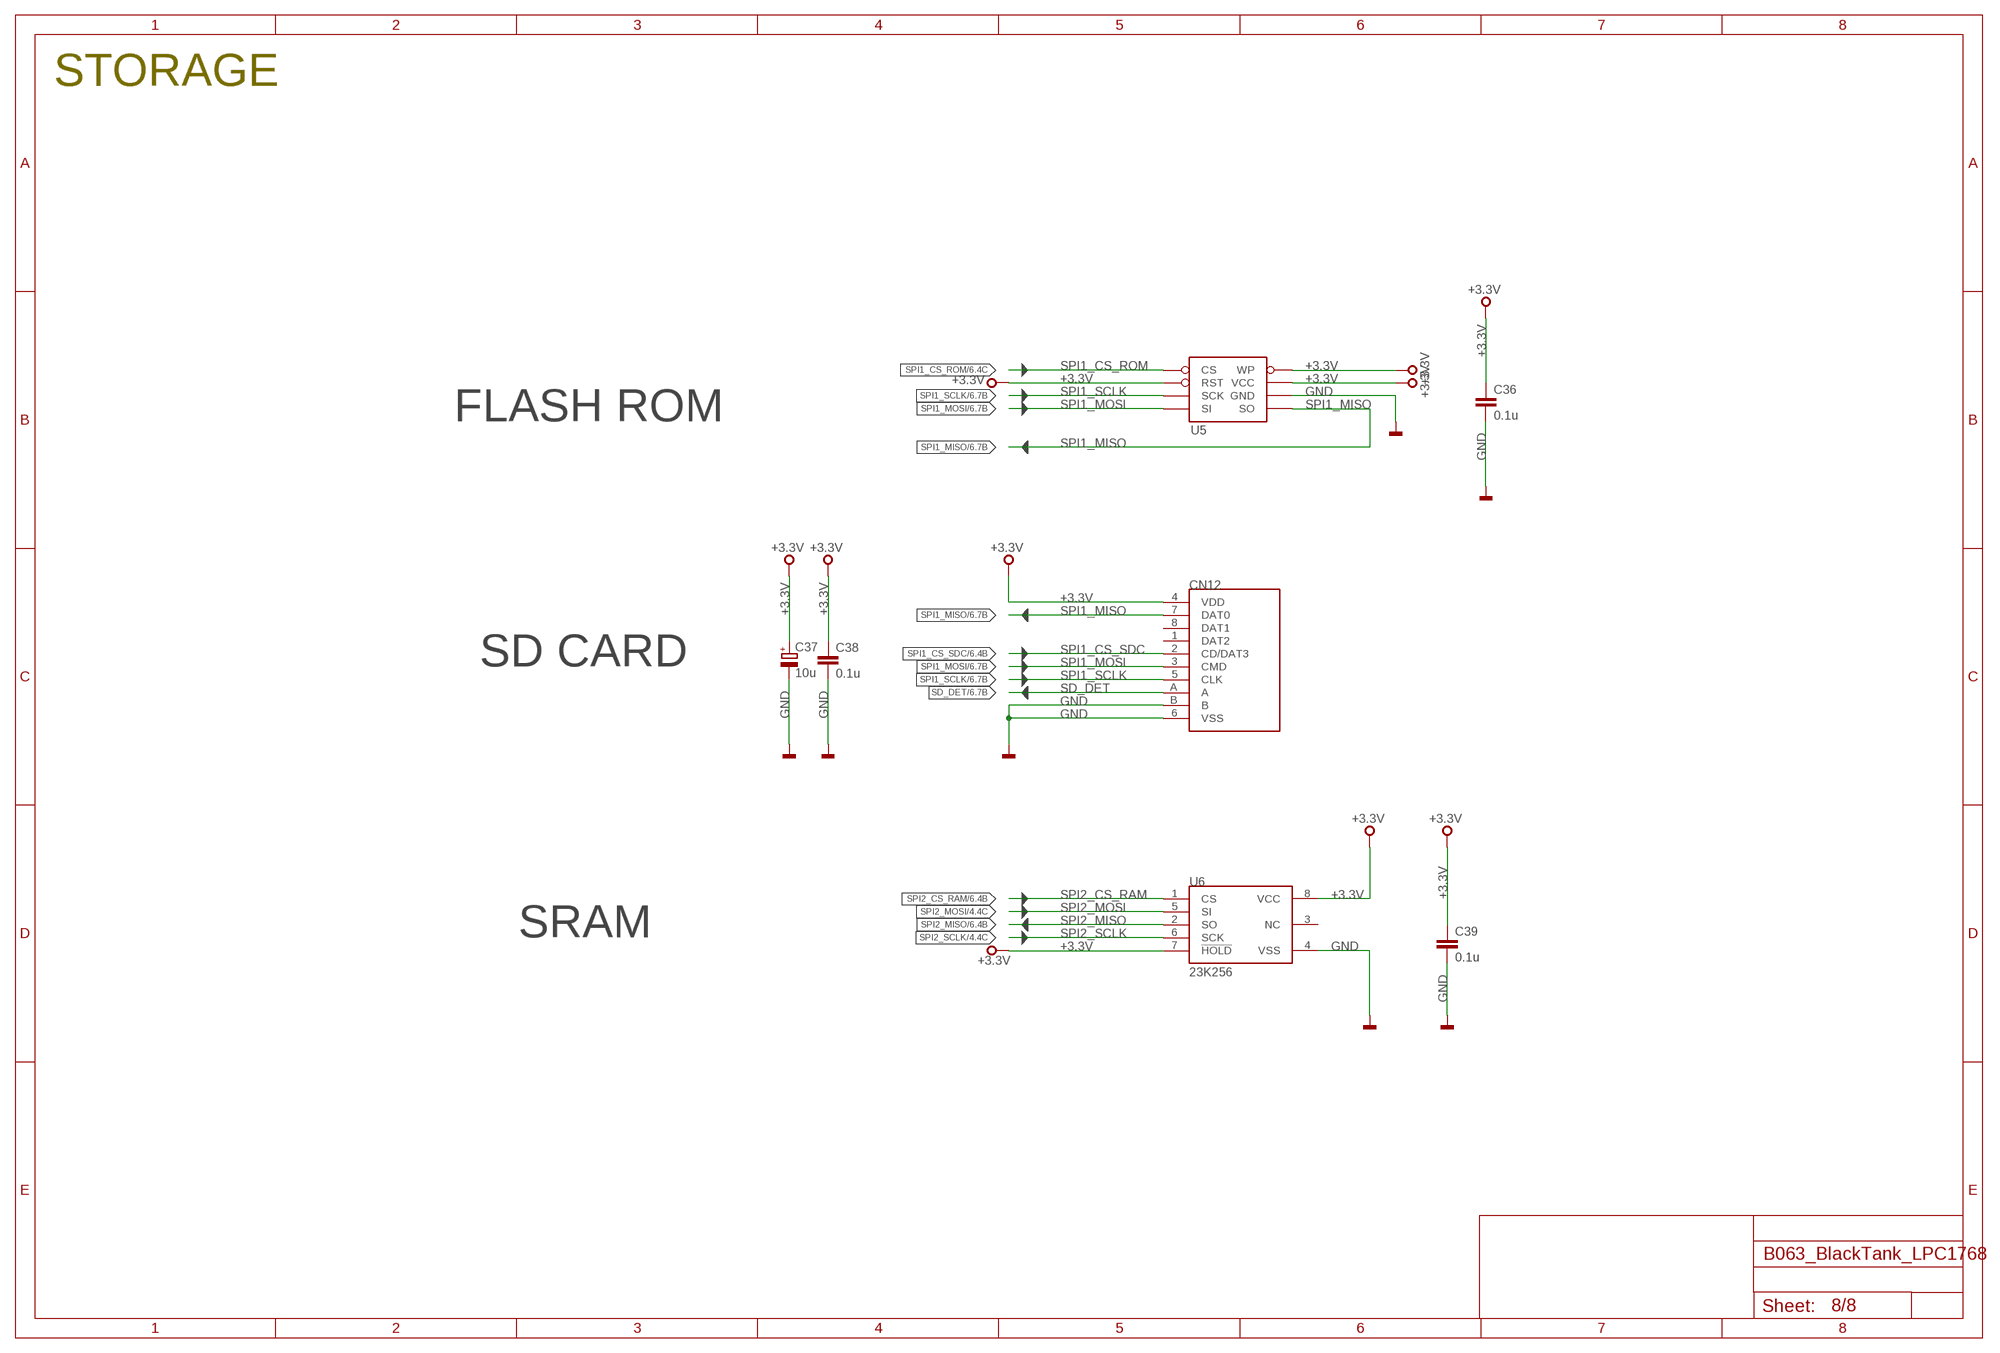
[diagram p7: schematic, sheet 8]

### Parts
C36  0.1u  C-EUC0603  [C0603]
C37  10u  CPOL-EU153CLV-0505  [153CLV-0505]
C38  0.1u  C-EUC0603  [C0603]
C39  0.1u  C-EUC0603  [C0603]
CN12  DM3AT-SF-PEJ  [DM3AT-SF-PEJ]
U5  AT45DB041B  [SO08]
U6  23K256  [TSSOP8]

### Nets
+3.3V [PWR]: C36.1 C37.+ C38.1 C39.1 CN12.4(VDD) U5.3(RST) U5.5(WP) U5.6(VCC) U6.7(!HOLD) U6.8(VCC) ; also sheet 3,4,5,6,7
GND [GND]: C36.2 C37.- C38.2 C39.2 CN12.6(VSS) CN12.B U5.7(GND) U6.4(VSS) ; also sheet 3,4,5,6,7
SD_DET: CN12.A ; also sheet 6
SPI1_CS_ROM: U5.4(CS) ; also sheet 6
SPI1_CS_SDC: CN12.2(CD/DAT3) ; also sheet 6
SPI1_MISO: CN12.7(DAT0) U5.8(SO) ; also sheet 6
SPI1_MOSI: CN12.3(CMD) U5.1(SI) ; also sheet 6
SPI1_SCLK: CN12.5(CLK) U5.2(SCK) ; also sheet 6
SPI2_CS_RAM: U6.1(CS) ; also sheet 6
SPI2_MISO: U6.2(SO) ; also sheet 6
SPI2_MOSI: U6.5(SI) ; also sheet 4,6
SPI2_SCLK: U6.6(SCK) ; also sheet 4,6
Unconnected: CN12.1(DAT2) CN12.8(DAT1) U6.3(NC)

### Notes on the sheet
- STORAGE
- FLASH ROM
- SD CARD
- SRAM

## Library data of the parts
C1 C2 C4 C5 C8 C10 C26-C28 C30-C32 C34-C36 C38 C39 = rcl:C-EU: CAPACITOR, European symbol
C3 C7 C9 C13 C20-C25 C29 C33 C37 = rcl:CPOL-EU: POLARIZED CAPACITOR, European symbol
C6 C11 C12 C14-C19 = mbed:C
CN1 = con-hirose:FH12-22S-0.5S: 0.5mm Pitch Connectors For FPC/FFC Source: Data sheet; OC_FARNELL: 1324551; OC_NEWARK: unknown
CN2-CN4 = con-hirose-df13:DF13-4P-1.25: DF13-4P 1.25mm Pitch Miniature Crimping Connector.
CN5 = mbed-connectors:JTAG-20: SUYIN Connector 20-pol
CN6 = con-berg:PN61729-S: BERG USB connector; OC_FARNELL: unknown; OC_NEWARK: unknown
CN7 = battery:CR2430H: LI BATTERY Varta
CN8-CN11 = cbs-switronic-industrial:ST-005
CN12 = cbs-hirose:DM3AT-SF-PEJ
D1 D2 = diode:MBR0520LT: SCHOTTKY BARRIER RECTIFIER
F1 = switch-raychem:SMD*F: PolySwitch (TM) Resettable Device
H1-H4 = holes:MOUNT-HOLE: MOUNTING HOLE with drill center marker
L1 L2 = rcl:L-US: INDUCTOR, American symbol
LED1-LED6 = mbed:LED
R1-R8 R16-R40 = mbed:R
R9-R15 = mbed-rlcq:R
RV1-RV4 = cbs-alps:RK09: POTENTIOMETER
SW1-SW4 = cbs-nikkai:HB2-15SKP4RM
SW5 SW6 = switch-tact:DTSM-3
TP1-TP11 = testpad:PTR1: TEST PIN
U1 = ftdichip:FT232R: Source: http://www.ftdichip.com/Documents/DataSheets/DS_FT232R_v104.pdf; MPN: FT232RL; OC_FARNELL: 1146032; OC_NEWARK: 91K9918
U2 = burr-brown:REG1117: 800mA and 1A Low Dropout (LDO) Positive Regulator 1.8V, 2.5V, 2.85V, 3.3V, 5V, and Adj; MPN: REG1117; OC_FARNELL: 1097566; OC_NEWARK: 14P6981
U3 = mbed:LPC1768
U4 = tlv320aic23b:TLV320AIC23B
U5 = SparkFun:AT45DB041B
U6 = cbs-atmel:23K256
X1 = LPC1768RefDesign:CRYSTAL: CRYSTAL
X2 = mbed:OSCILLATOR

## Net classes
0 default: width 0.152 mm, drill 0.254 mm, clearance 0.152 mm
1 PWR: width 0.305 mm, drill 0.254 mm, clearance 0.152 mm
2 GND: width 0.305 mm, drill 0.254 mm, clearance 0.152 mm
